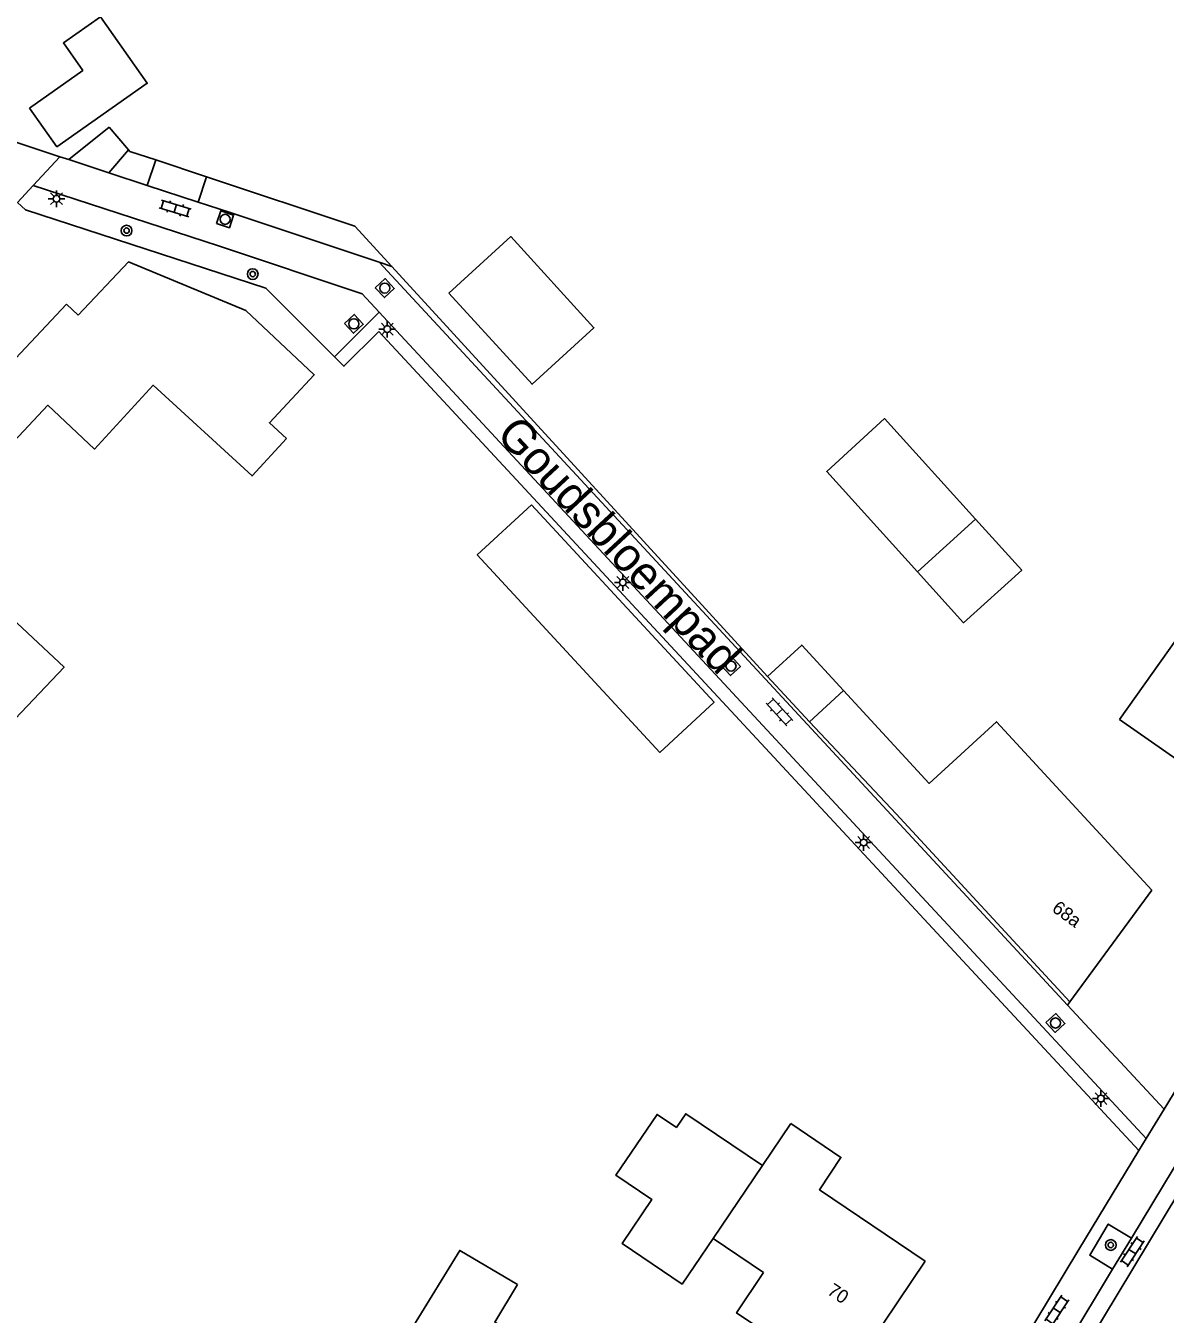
# Model space of a CAD drawing. Extents: x 136000 to 141014, y 402000 to 403500.
# Drawn here: x 137612.8 to 137697.7, y 402166.6 to 402262.7 of the extents above; entities that cross this region are included whole.
import ezdxf

# ---------------------------------------------------------------- set-up
doc = ezdxf.new("R2010")
doc.units = 0
for name, color, linetype in [('gg-afsc-erfafscheiding', 7, 'Continuous'), ('gg-anno-huisnummerreeks BGT', 7, 'Continuous'), ('gg-anno-openbare ruimte label', 7, 'Continuous'), ('gg-bbg-bijgebouw', 7, 'Continuous'), ('gg-bbg-gedigitaliseerde bebouwing', 7, 'Continuous'), ('gg-bbg-gedigitaliseerde bijgebouw', 7, 'Continuous'), ('gg-bbg-hoofdgebouw', 7, 'Continuous'), ('gg-bbg-luifel en loopbrug', 7, 'Continuous'), ('gg-bbg-tussenscheiding', 7, 'Continuous'), ('gg-knt-verharding', 7, 'Continuous'), ('gg-knt-verharding nz', 7, 'Continuous'), ('gt-bbg-plantopografie pand', 7, 'Continuous'), ('gt-grn-groengrens', 7, 'Continuous'), ('gt-grn-weggrens', 7, 'Continuous'), ('gt-symb-boom', 7, 'Continuous'), ('gt-symb-klinker verharding', 7, 'Continuous'), ('gt-symb-lichtmast', 7, 'Continuous'), ('gt-symb-rioolschacht', 7, 'Continuous')]:
    doc.layers.add(name, color=color, linetype=linetype)

# ---------------------------------------------------------------- blocks, each defined once
blk = doc.blocks.new('gt0-BOOM')
at = {"layer": 'gt-symb-boom'}
for radius in [0.4, 0.2]:
    blk.add_circle((0, 0), radius, dxfattribs=at)
blk = doc.blocks.new('gt0-LMAST')
at = {"layer": 'gt-symb-lichtmast'}
for p, q in [((-0.182, 0.173), (-0.447, 0.438)), ((-0.005, 0.246), (-0.005, 0.621)), ((0.172, 0.173), (0.437, 0.438)), ((-0.255, -0.004), (-0.63, -0.004)), ((-0.182, -0.181), (-0.447, -0.446)), ((-0.005, -0.254), (-0.005, -0.629)), ((0.437, -0.446), (0.172, -0.181)), ((0.245, -0.004), (0.62, -0.004))]:
    blk.add_line(p, q, dxfattribs=at)
blk.add_circle((-0.005, -0.004), 0.25, dxfattribs=at)
blk = doc.blocks.new('gt0-KL1')
at = {"layer": 'gt-symb-klinker verharding'}
for p, q in [((-1.15, 0.3), (1.15, 0.3)), ((-1, -0.3), (-1, 0.3)), ((-0.5, 0.3), (-0.5, 0.45)), ((0, -0.3), (0, 0.3)), ((0.5, 0.3), (0.5, 0.45)), ((1, -0.3), (1, 0.3)), ((-1.15, -0.3), (1.15, -0.3)), ((-0.5, -0.45), (-0.5, -0.3)), ((0.5, -0.45), (0.5, -0.3))]:
    blk.add_line(p, q, dxfattribs=at)
blk = doc.blocks.new('gt0-RS')
at = {"layer": 'gt-symb-rioolschacht'}
blk.add_lwpolyline([(-0.5, -0.5), (0.5, -0.5), (0.5, 0.5), (-0.5, 0.5)], close=True, dxfattribs=at)
blk.add_circle((0, 0), 0.375, dxfattribs=at)

msp = doc.modelspace()

# ---------------------------------------------------------------- linework, layer by layer
at = {"layer": 'gg-afsc-erfafscheiding'}
for p, q in [((137618.98, 402255.168), (137620.431, 402253.464)), ((137622.447, 402252.714), (137626.245, 402251.454)), ((137626.245, 402251.454), (137637.295, 402247.787)), ((137640.06, 402244.777), (137637.295, 402247.787)), ((137668.089, 402214.192), (137640.06, 402244.777)), ((137639.107, 402241.368), (137635.781, 402238.038))]:
    msp.add_line(p, q, dxfattribs=at)
for points in [[(137620.431, 402253.464), (137620.526, 402253.352), (137622.447, 402252.714)], [(137635.781, 402238.038), (137630.651, 402243.161), (137612.748, 402248.99), (137612.141, 402249.553)]]:
    msp.add_lwpolyline(points, dxfattribs=at)
at = {"layer": 'gg-bbg-bijgebouw'}
msp.add_line((137679.272, 402221.989), (137683.59, 402225.929), dxfattribs=at)
for points in [[(137644.316, 402242.782), (137648.924, 402246.999), (137655.132, 402240.202), (137650.524, 402235.985), (137644.316, 402242.782)], [(137679.272, 402221.989), (137672.494, 402229.486), (137676.812, 402233.426), (137683.59, 402225.929)]]:
    msp.add_lwpolyline(points, dxfattribs=at)
at = {"layer": 'gg-bbg-gedigitaliseerde bebouwing'}
for p, q in [((137669.814, 402180.843), (137667.697, 402177.713)), ((137667.78, 402169.74), (137664.023, 402172.281))]:
    msp.add_line(p, q, dxfattribs=at)
for points in [[(137632.194, 402231.928), (137629.642, 402229.146), (137622.262, 402235.916), (137617.89, 402231.15), (137614.4, 402234.42), (137608.61, 402228.25), (137603.37, 402233.17)], [(137715.34, 402224.45), (137707.728, 402229.859), (137694.325, 402210.969)], [(137599.97, 402229.51), (137615.61, 402214.89), (137611.5, 402210.53), (137600.38, 402220.88), (137596.328, 402216.534), (137594.712, 402214.868)], [(137649.42, 402168.83), (137645.12, 402171.38), (137641.676, 402165.751), (137649.197, 402161.149), (137643.414, 402151.698), (137651.73, 402146.61)], [(137667.78, 402169.74), (137665.768, 402166.724), (137673.68, 402161.42)]]:
    msp.add_lwpolyline(points, dxfattribs=at)
at = {"layer": 'gg-bbg-gedigitaliseerde bijgebouw'}
for points in [[(137613.038, 402256.589), (137615.08, 402253.693), (137621.812, 402258.44), (137618.326, 402263.384), (137615.566, 402261.439), (137617.011, 402259.39), (137613.038, 402256.589)], [(137667.697, 402177.713), (137661.979, 402181.58), (137661.284, 402180.552), (137659.845, 402181.525), (137656.772, 402176.982), (137659.455, 402175.168), (137657.239, 402171.892), (137661.713, 402168.866), (137664.023, 402172.281)]]:
    msp.add_lwpolyline(points, dxfattribs=at)
at = {"layer": 'gg-bbg-hoofdgebouw'}
for p, q in [((137615.79, 402241.95), (137616.668, 402241.131)), ((137673.743, 402213.144), (137671.207, 402210.805)), ((137671.207, 402210.805), (137677.673, 402203.938)), ((137702, 402205.61), (137694.325, 402210.969)), ((137677.673, 402203.938), (137690.63, 402189.91)), ((137690.63, 402189.91), (137696.74, 402198.26)), ((137673.68, 402161.42), (137679.836, 402170.588))]:
    msp.add_line(p, q, dxfattribs=at)
for points in [[(137632.194, 402231.928), (137630.924, 402233.119), (137634.276, 402236.693), (137629.175, 402241.476), (137620.409, 402245.113), (137616.668, 402241.131)], [(137603.37, 402233.17), (137609.36, 402239.59), (137611.62, 402237.5), (137615.79, 402241.95)], [(137696.74, 402198.26), (137685.149, 402210.818), (137680.136, 402206.211), (137673.743, 402213.144)], [(137679.836, 402170.588), (137671.947, 402175.9), (137673.554, 402178.316), (137669.814, 402180.843)], [(137651.73, 402146.61), (137655.94, 402153.59), (137662.91, 402149.42), (137666.22, 402154.96), (137647.75, 402166.02), (137649.42, 402168.83)]]:
    msp.add_lwpolyline(points, dxfattribs=at)
at = {"layer": 'gg-bbg-luifel en loopbrug'}
msp.add_line((137671.207, 402210.805), (137668.089, 402214.192), dxfattribs=at)
for points in [[(137683.59, 402225.929), (137687.037, 402222.117), (137682.701, 402218.196), (137679.272, 402221.989)], [(137673.743, 402213.144), (137670.627, 402216.529), (137668.089, 402214.192)]]:
    msp.add_lwpolyline(points, dxfattribs=at)
at = {"layer": 'gg-bbg-tussenscheiding'}
msp.add_line((137664.023, 402172.281), (137667.697, 402177.713), dxfattribs=at)
at = {"layer": 'gg-knt-verharding'}
for p, q in [((137615.969, 402252.737), (137618.98, 402255.168)), ((137615.306, 402252.954), (137615.969, 402252.737)), ((137620.431, 402253.464), (137618.944, 402251.763)), ((137621.819, 402250.821), (137618.944, 402251.763)), ((137613.32, 402250.82), (137612.141, 402249.553)), ((137625.622, 402249.576), (137621.819, 402250.821)), ((137690.463, 402189.682), (137639.119, 402245.091)), ((137639.107, 402241.368), (137696.321, 402179.717)), ((137697.659, 402181.915), (137690.463, 402189.682)), ((137696.321, 402179.717), (137697.659, 402181.915)), ((137695.781, 402178.829), (137696.321, 402179.717)), ((137693.821, 402169.989), (137695.216, 402172.298))]:
    msp.add_line(p, q, dxfattribs=at)
for points in [[(137601.343, 402244.681), (137610.82, 402254.89), (137611.41, 402254.23), (137615.306, 402252.954)], [(137639.107, 402241.368), (137637.843, 402242.73), (137627.14, 402246.31), (137613.32, 402250.82)], [(137639.119, 402245.091), (137627.93, 402248.82), (137625.622, 402249.576)], [(137697.659, 402181.915), (137701.257, 402187.824), (137703.372, 402191.378), (137712.386, 402206.284)], [(137680.358, 402153.304), (137691.287, 402171.449), (137695.781, 402178.829)], [(137695.216, 402172.298), (137693.491, 402173.34), (137692.11, 402171.023), (137693.821, 402169.989)]]:
    msp.add_lwpolyline(points, dxfattribs=at)
at = {"layer": 'gg-knt-verharding nz'}
for p, q in [((137704.755, 402185.699), (137691.073, 402162.952)), ((137695.216, 402172.298), (137701.613, 402182.885)), ((137689.958, 402163.597), (137693.821, 402169.989))]:
    msp.add_line(p, q, dxfattribs=at)
at = {"layer": 'gt-bbg-plantopografie pand'}
msp.add_lwpolyline([(137650.465, 402226.988), (137664.096, 402212.267), (137660.06, 402208.53), (137646.43, 402223.251), (137650.465, 402226.988)], dxfattribs=at)
at = {"layer": 'gt-grn-groengrens'}
for p, q in [((137621.819, 402250.821), (137622.447, 402252.714)), ((137626.245, 402251.454), (137625.622, 402249.576)), ((137639.119, 402245.091), (137640.06, 402244.777)), ((137639.081, 402239.926), (137695.781, 402178.829)), ((137690.63, 402189.91), (137690.463, 402189.682))]:
    msp.add_line(p, q, dxfattribs=at)
msp.add_lwpolyline([(137639.081, 402239.926), (137636.489, 402237.331), (137635.781, 402238.038)], dxfattribs=at)
at = {"layer": 'gt-grn-weggrens'}
for p, q in [((137613.32, 402250.82), (137615.306, 402252.954)), ((137615.969, 402252.737), (137618.944, 402251.763))]:
    msp.add_line(p, q, dxfattribs=at)

# ---------------------------------------------------------------- block references
at = {"layer": 'gt-symb-boom'}
for p in [(137620.277, 402247.444), (137629.683, 402244.203), (137693.68, 402171.785)]:
    msp.add_blockref('gt0-BOOM', p, dxfattribs=at)
at = {"layer": 'gt-symb-klinker verharding'}
for p, rotation in [((137623.903, 402249.096), 163.19645198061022), ((137668.976, 402211.553), 131.99999127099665), ((137695.288, 402171.293), 56.500599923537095), ((137689.658, 402166.914), 56.50059992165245)]:
    msp.add_blockref('gt0-KL1', p, dxfattribs=dict(at, rotation=rotation))
at = {"layer": 'gt-symb-lichtmast'}
for p in [(137615.056, 402249.826), (137639.725, 402240.104), (137657.288, 402221.209), (137675.255, 402201.81), (137692.955, 402182.709)]:
    msp.add_blockref('gt0-LMAST', p, dxfattribs=at)
at = {"layer": 'gt-symb-rioolschacht'}
for p, rotation in [((137627.623, 402248.284), -18.126812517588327), ((137639.53, 402243.16), -47.187036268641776), ((137637.227, 402240.49), -47.187036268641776), ((137665.357, 402214.963), -47.187036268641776), ((137689.552, 402188.345), -47.187036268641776)]:
    msp.add_blockref('gt0-RS', p, dxfattribs=dict(at, rotation=rotation))

# ---------------------------------------------------------------- texts
at = {"layer": 'gg-anno-huisnummerreeks BGT'}
for s, rotation, p in [('68a', 323.8, (137689.222, 402196.731)), ('70', 326.1, (137672.46, 402168.172))]:
    msp.add_text(s, height=1, rotation=rotation, dxfattribs=at).set_placement(p)
at = {"layer": 'gg-anno-openbare ruimte label'}
msp.add_text('Goudsbloempad', height=2.5, rotation=312.9, dxfattribs=at).set_placement((137647.761, 402232.151))

doc.saveas('drawing.dxf')
